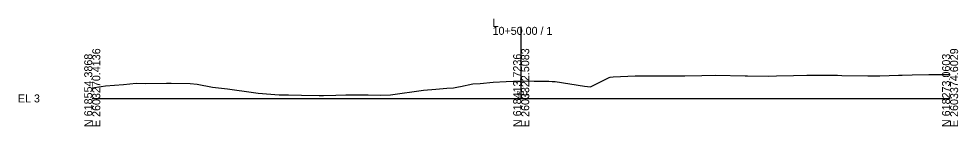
# Model space of a CAD drawing. Extents: x -26 to 2605155, y -10 to 618566.
# Drawn here: x -25.7 to 302.8, y -9.7 to 27.8 of the extents above; entities that cross this region are included whole.
import ezdxf

# ---------------------------------------------------------------- set-up
doc = ezdxf.new("R2010")
doc.units = 0
for name, color, linetype in [('Default', 7, 'Continuous'), ('Exist Cross Section Cell', 7, 'Continuous'), ('Exist XS Center Line Elevation Label', 7, 'Continuous'), ('Exist XS Ground Line', 7, 'Continuous')]:
    doc.layers.add(name, color=color, linetype=linetype)

msp = doc.modelspace()

# ---------------------------------------------------------------- linework, layer by layer
at = {"layer": 'Exist Cross Section Cell'}
for p, q in [((150, 0), (150, 24.99)), ((0, 0), (150, 0)), ((150, 0), (300, 0))]:
    msp.add_line(p, q, dxfattribs=at)
at = {"layer": 'Exist XS Ground Line'}
msp.add_lwpolyline([(0, 3.64), (3.09, 4.17), (4.68, 4.36), (10.87, 4.83), (15.34, 5.32), (18.66, 5.25), (26.01, 5.3), (26.44, 5.28), (27.6, 5.27), (34.22, 5.16), (36.67, 4.95), (42, 3.96), (47.33, 3.31), (56.4, 2.04), (58, 1.81), (65.35, 1.22), (68.66, 1.23), (73.13, 1.13), (79.32, 0.98), (80.91, 1.02), (85.19, 1.14), (88.69, 1.25), (89.99, 1.28), (96.47, 1.22), (100.65, 1.17), (104.26, 1.23), (115.89, 2.85), (120.18, 3.24), (124.03, 3.63), (126.3, 3.71), (128.08, 4.03), (128.73, 4.16), (133.11, 5.04), (135.66, 5.26), (140.25, 5.65), (144.7, 5.87), (149.86, 6.11), (154.57, 6.06), (159.73, 6.02), (160.8, 5.94), (161.83, 5.86), (172.19, 4.31), (174.23, 4), (180.82, 7.27), (181.16, 7.47), (182.18, 7.52), (189.85, 7.9), (196.63, 7.94), (200.37, 7.91), (207.29, 7.91), (213.2, 8.02), (217.95, 8.11), (228.3, 7.87), (228.62, 7.86), (229.16, 7.86), (236.55, 7.77), (239.28, 7.91), (245.23, 7.96), (249.94, 8.12), (252.11, 8.1), (257.95, 8.1), (259.89, 8.09), (260.61, 8.09), (262.17, 8.05), (271.27, 7.86), (275.45, 7.92), (281.94, 8.07), (283.24, 8.11), (286.75, 8.19), (292.6, 8.32), (296.04, 8.33), (300, 8.31)], dxfattribs=at)

# ---------------------------------------------------------------- texts
at = {"layer": 'Default'}
msp.add_text('-', height=0.0001, dxfattribs=at).set_placement((0, 0))
at = {"layer": 'Exist Cross Section Cell'}
for s, p in [('L', (140, 24.99)), ('10+50.00 / 1', (140, 22.19)), ('EL 3', (-26, -1.4))]:
    msp.add_text(s, height=2.8, dxfattribs=at).set_placement(p)
for s, p in [('E 2603270.4136', (2.8, -10)), ('E 2603322.5083', (152.8, -10)), ('E 2603374.6029', (302.8, -10)), ('N 618554.3868', (0, -10)), ('N 618413.7236', (150, -10)), ('N 618273.0603', (300, -10))]:
    msp.add_text(s, height=2.8, rotation=90, dxfattribs=at).set_placement(p)
at = {"layer": 'Exist XS Center Line Elevation Label'}
msp.add_text('9.11', height=1.5, dxfattribs=at).set_placement((148.42, 1.11))

doc.saveas('drawing.dxf')
